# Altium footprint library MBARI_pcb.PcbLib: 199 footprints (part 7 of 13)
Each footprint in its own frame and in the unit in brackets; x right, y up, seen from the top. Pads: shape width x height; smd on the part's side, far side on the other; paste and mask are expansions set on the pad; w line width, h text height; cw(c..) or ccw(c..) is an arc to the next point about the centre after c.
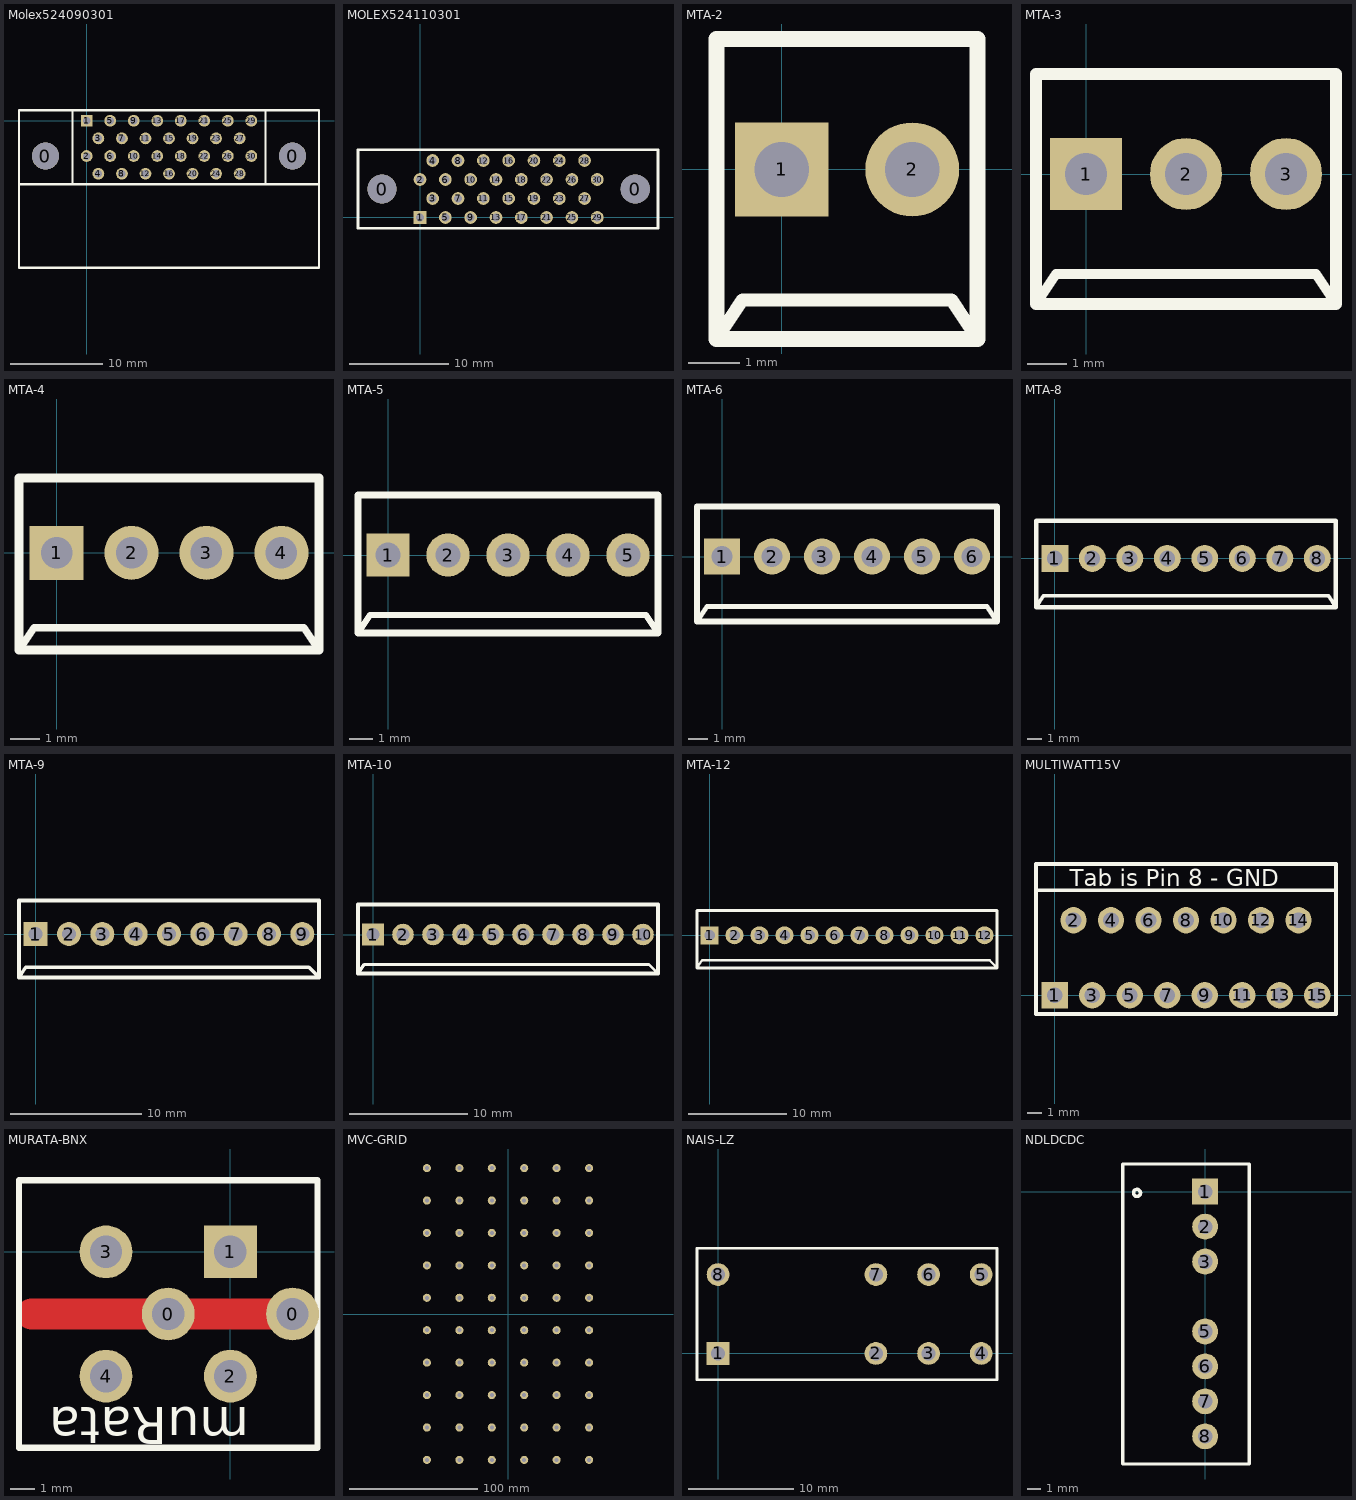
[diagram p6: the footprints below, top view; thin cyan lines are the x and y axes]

## Molex524090301 [mil]
pads (32):
  round 115 hole 115: 0(-175,-150) 0(875,-150)
  rect 50x50 hole 32: 1(0,0)
  round 50 hole 32: 2(0,-150) 3(50,-75) 4(50,-225) 5(100,0) 6(100,-150) 7(150,-75) 8(150,-225) 9(200,0) 10(200,-150) 11(250,-75) 12(250,-225) 13(300,0) 14(300,-150) 15(350,-75) 16(350,-225) 17(400,0) 18(400,-150) 19(450,-75) 20(450,-225) 21(500,0) 22(500,-150) 23(550,-75) 24(550,-225) 25(600,0) 26(600,-150) 27(650,-75) 28(650,-225) 29(700,0) 30(700,-150)
TopOverlay:
  lines w10: -287.5,-270 987.5,-270 ; -60,-270 -60,45 ; 760,-270 760,45 ; -287.5,-625 987.5,-625 987.5,45 -287.5,45 -287.5,-625

## MOLEX524110301 [mil]
pads (32):
  round 115 hole 115: 0(-150,112.5) 0(850,112.5)
  rect 50x50 hole 32: 1(0,0)
  round 50 hole 32: 2(0,150) 3(50,75) 4(50,225) 5(100,0) 6(100,150) 7(150,75) 8(150,225) 9(200,0) 10(200,150) 11(250,75) 12(250,225) 13(300,0) 14(300,150) 15(350,75) 16(350,225) 17(400,0) 18(400,150) 19(450,75) 20(450,225) 21(500,0) 22(500,150) 23(550,75) 24(550,225) 25(600,0) 26(600,150) 27(650,75) 28(650,225) 29(700,0) 30(700,150)
TopOverlay:
  lines w10: -245,-42.5 940,-42.5 940,267.5 -245,267.5 -245,-42.5

## MTA-2 [mil]
pads (2):
  rect 72x72 hole 42: 1(0,0)
  round 72 hole 42: 2(100,0)
TopOverlay:
  lines w10: -50,-130 -30,-100 130,-100 150,-130
  lines w12: -50,-130 150,-130 150,100 -50,100 -50,-130

## MTA-3 [mil]
pads (3):
  rect 72x72 hole 42: 1(0,0)
  round 72 hole 42: 2(100,0) 3(200,0)
TopOverlay:
  lines w10: -50,-130 -30,-100 230,-100 250,-130
  lines w12: -50,-130 250,-130 250,100 -50,100 -50,-130

## MTA-4 [mil]
pads (4):
  rect 72x72 hole 42: 1(0,0)
  round 72 hole 42: 2(100,0) 3(200,0) 4(300,0)
TopOverlay:
  lines w10: -50,-130 -30,-100 330,-100 350,-130
  lines w12: -50,-130 -50,100 350,100 350,-130 -50,-130

## MTA-5 [mil]
pads (5):
  rect 72x72 hole 42: 1(0,0)
  round 72 hole 42: 2(100,0) 3(200,0) 4(300,0) 5(400,0)
TopOverlay:
  lines w10: -50,-130 -30,-100 430,-100 450,-130
  lines w12: -50,-130 450,-130 450,100 -50,100 -50,-130

## MTA-6 [mil]
pads (6):
  rect 72x72 hole 42: 1(0,0)
  round 72 hole 42: 2(100,0) 3(200,0) 4(300,0) 5(400,0) 6(500,0)
TopOverlay:
  lines w10: -50,-130 -30,-100 530,-100 550,-130
  lines w12: -50,-130 550,-130 550,100 -50,100 -50,-130

## MTA-8 [mil]
pads (8):
  rect 72x72 hole 42: 1(0,0)
  round 72 hole 42: 2(100,0) 3(200,0) 4(300,0) 5(400,0) 6(500,0) 7(600,0) 8(700,0)
TopOverlay:
  lines w10: -50,-130 -30,-100 730,-100 750,-130
  lines w12: -50,-130 -50,100 750,100 750,-130 -50,-130

## MTA-9 [mil]
pads (9):
  rect 72x72 hole 42: 1(0,0)
  round 72 hole 42: 2(100,0) 3(200,0) 4(300,0) 5(400,0) 6(500,0) 7(600,0) 8(700,0) 9(800,0)
TopOverlay:
  lines w10: -50,-130 -30,-100 820,-100 850,-130
  lines w12: -50,-130 850,-130 850,100 -50,100 -50,-130

## MTA-10 [mil]
pads (10):
  rect 72x72 hole 42: 1(0,0)
  round 72 hole 42: 2(100,0) 3(200,0) 4(300,0) 5(400,0) 6(500,0) 7(600,0) 8(700,0) 9(800,0) 10(900,0)
TopOverlay:
  lines w10: -50,-130 -30,-100 920,-100 950,-130
  lines w12: -50,-130 950,-130 950,100 -50,100 -50,-130

## MTA-12 [mil]
pads (12):
  rect 72x72 hole 42: 1(0,0)
  round 72 hole 42: 2(100,0) 3(200,0) 4(300,0) 5(400,0) 6(500,0) 7(600,0) 8(700,0) 9(800,0) 10(900,0) 11(1000,0) 12(1100,0)
TopOverlay:
  lines w10: -50,-130 -30,-100 1120,-100 1150,-130
  lines w12: -50,-130 1150,-130 1150,100 -50,100 -50,-130

## MULTIWATT15V [mil]
pads (15):
  rect 70x70 hole 42: 1(0,0)
  round 70 hole 42: 2(50,200) 3(100,0) 4(150,200) 5(200,0) 6(250,200) 7(300,0) 8(350,200) 9(400,0) 10(450,200) 11(500,0) 12(550,200) 13(600,0) 14(650,200) 15(700,0)
TopOverlay:
  lines w10: -50,280 750,280 ; -50,-50 750,-50 750,350 -50,350 -50,-50
  text "Tab is Pin 8 - GND" at 40,290 h45

## MURATA-BNX [mil]
pads (6):
  round 85 hole 52: 0(-100,-100) 0(100,-100) 2(0,-200) 3(-200,0) 4(-200,-200)
  rect 85x85 hole 52: 1(0,0)
TopLayer:
  lines w50: -320,-100 100,-100
TopOverlay:
  lines w10: -340,-315 -340,115 140,115 140,-315 -340,-315
  text "muRata" at 30,-250 h60

## MVC-GRID [mil]
pads (60):
  round 250 hole 125: 00(-2500,4500) 01(-2500,3500) 02(-2500,2500) 03(-2500,1500) 04(-2500,500) 05(-2500,-500) 06(-2500,-1500) 07(-2500,-2500) 08(-2500,-3500) 09(-2500,-4500) 10(-1500,4500) 11(-1500,3500) 12(-1500,2500) 13(-1500,1500) 14(-1500,500) 15(-1500,-500) 16(-1500,-1500) 17(-1500,-2500) 18(-1500,-3500) 19(-1500,-4500) 20(-500,4500) 21(-500,3500) 22(-500,2500) 23(-500,1500) 24(-500,500) 25(-500,-500) 26(-500,-1500) 27(-500,-2500) 28(-500,-3500) 29(-500,-4500) 30(500,4500) 31(500,3500) 32(500,2500) 33(500,1500) 34(500,500) 35(500,-500) 36(500,-1500) 37(500,-2500) 38(500,-3500) 39(500,-4500) 40(1500,4500) 41(1500,3500) 42(1500,2500) 43(1500,1500) 44(1500,500) 45(1500,-500) 46(1500,-1500) 47(1500,-2500) 48(1500,-3500) 49(1500,-4500) 50(2500,4500) 51(2500,3500) 52(2500,2500) 53(2500,1500) 54(2500,500) 55(2500,-500) 56(2500,-1500) 57(2500,-2500) 58(2500,-3500) 59(2500,-4500)

## NAIS-LZ [mil] "NAIS LZ Relay"
height 24330.71
pads (8):
  rect 85x85 hole 52: 1(0,0)
  round 85 hole 52: 2(590.55,0) 3(787.4,0) 4(984.25,0) 5(984.25,295.28) 6(787.4,295.28) 7(590.55,295.28) 8(0,295.28)
TopOverlay:
  lines w10: -78.74,-98.43 -78.74,393.7 1043.31,393.7 1043.31,-98.43 -78.74,-98.43

## NDLDCDC [mil]
pads (7):
  rect 74x74 hole 42: 1(0,0)
  round 74 hole 42: 2(0,-100) 3(0,-200) 5(0,-400) 6(0,-500) 7(0,-600) 8(0,-700)
TopOverlay:
  circle w10: c-195.04,-3.54 r10
  lines w10: -236.22,-779.29 -236.22,79.13 -36.22,79.13 126.46,79.13 126.46,-779.29 -236.22,-779.29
